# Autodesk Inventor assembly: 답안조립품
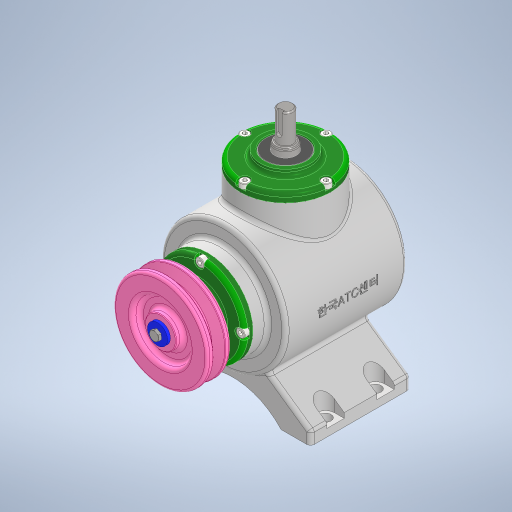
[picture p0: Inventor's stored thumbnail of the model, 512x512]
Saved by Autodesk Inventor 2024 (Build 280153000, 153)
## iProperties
Created: 2023-08
Part Number: 답안조립품
Document SubType Name: Assembly
Designer: Owner
Author: Owner
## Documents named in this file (17)
- C:\Users\Owner\Desktop\730813V1007\답안조립품.iam
- C:\Users\Owner\Desktop\730813V1007\본체.ipt
- C:\Users\Owner\Desktop\730813V1007\V-벨트풀리.ipt
- C:\Users\Owner\Desktop\730813V1007\메인 베벨기어.ipt
- C:\Users\Owner\Desktop\730813V1007\메인 축.ipt
- 메인 축.ipt
- C:\Users\Owner\Desktop\730813V1007\베어링 6203.ipt
- C:\Users\Owner\Desktop\730813V1007\볼트 M4 x 10.ipt
- C:\Users\Owner\Desktop\730813V1007\서브 베벨기어.ipt
- C:\Users\Owner\Desktop\730813V1007\서브 축.ipt
- 서브 축.ipt
- C:\Users\Owner\Desktop\730813V1007\오일실 17 x 32 x 8.ipt
- C:\Users\Owner\Desktop\730813V1007\와셔 4 x 16.ipt
- C:\Users\Owner\Desktop\730813V1007\육각볼트 M4 x 8.ipt
- C:\Users\Owner\Desktop\730813V1007\커버.ipt
- C:\Users\Owner\Desktop\730813V1007\키 4 x 4 x 14.ipt
- C:\Users\Owner\Desktop\730813V1007\키 5 x 5 x 14.ipt
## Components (1 placed, 1 different names)
1. V-벨트풀리:1 — 플러쉬:1
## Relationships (1: Flush 1)
- 플러쉬:1 [Flush]: V-벨트풀리:1
